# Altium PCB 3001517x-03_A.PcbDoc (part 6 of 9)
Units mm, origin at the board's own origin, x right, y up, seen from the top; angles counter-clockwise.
Board outline 100 x 72 mm, 10 copper layers (Top, GND_2, Signal_3, Signal_4, PWR_5, GND_6, Signal_7, Signal_8, GND_9, Bottom), stack 1.6 mm thick; 602 components, 497 nets, 2372 pads, 1602 vias.
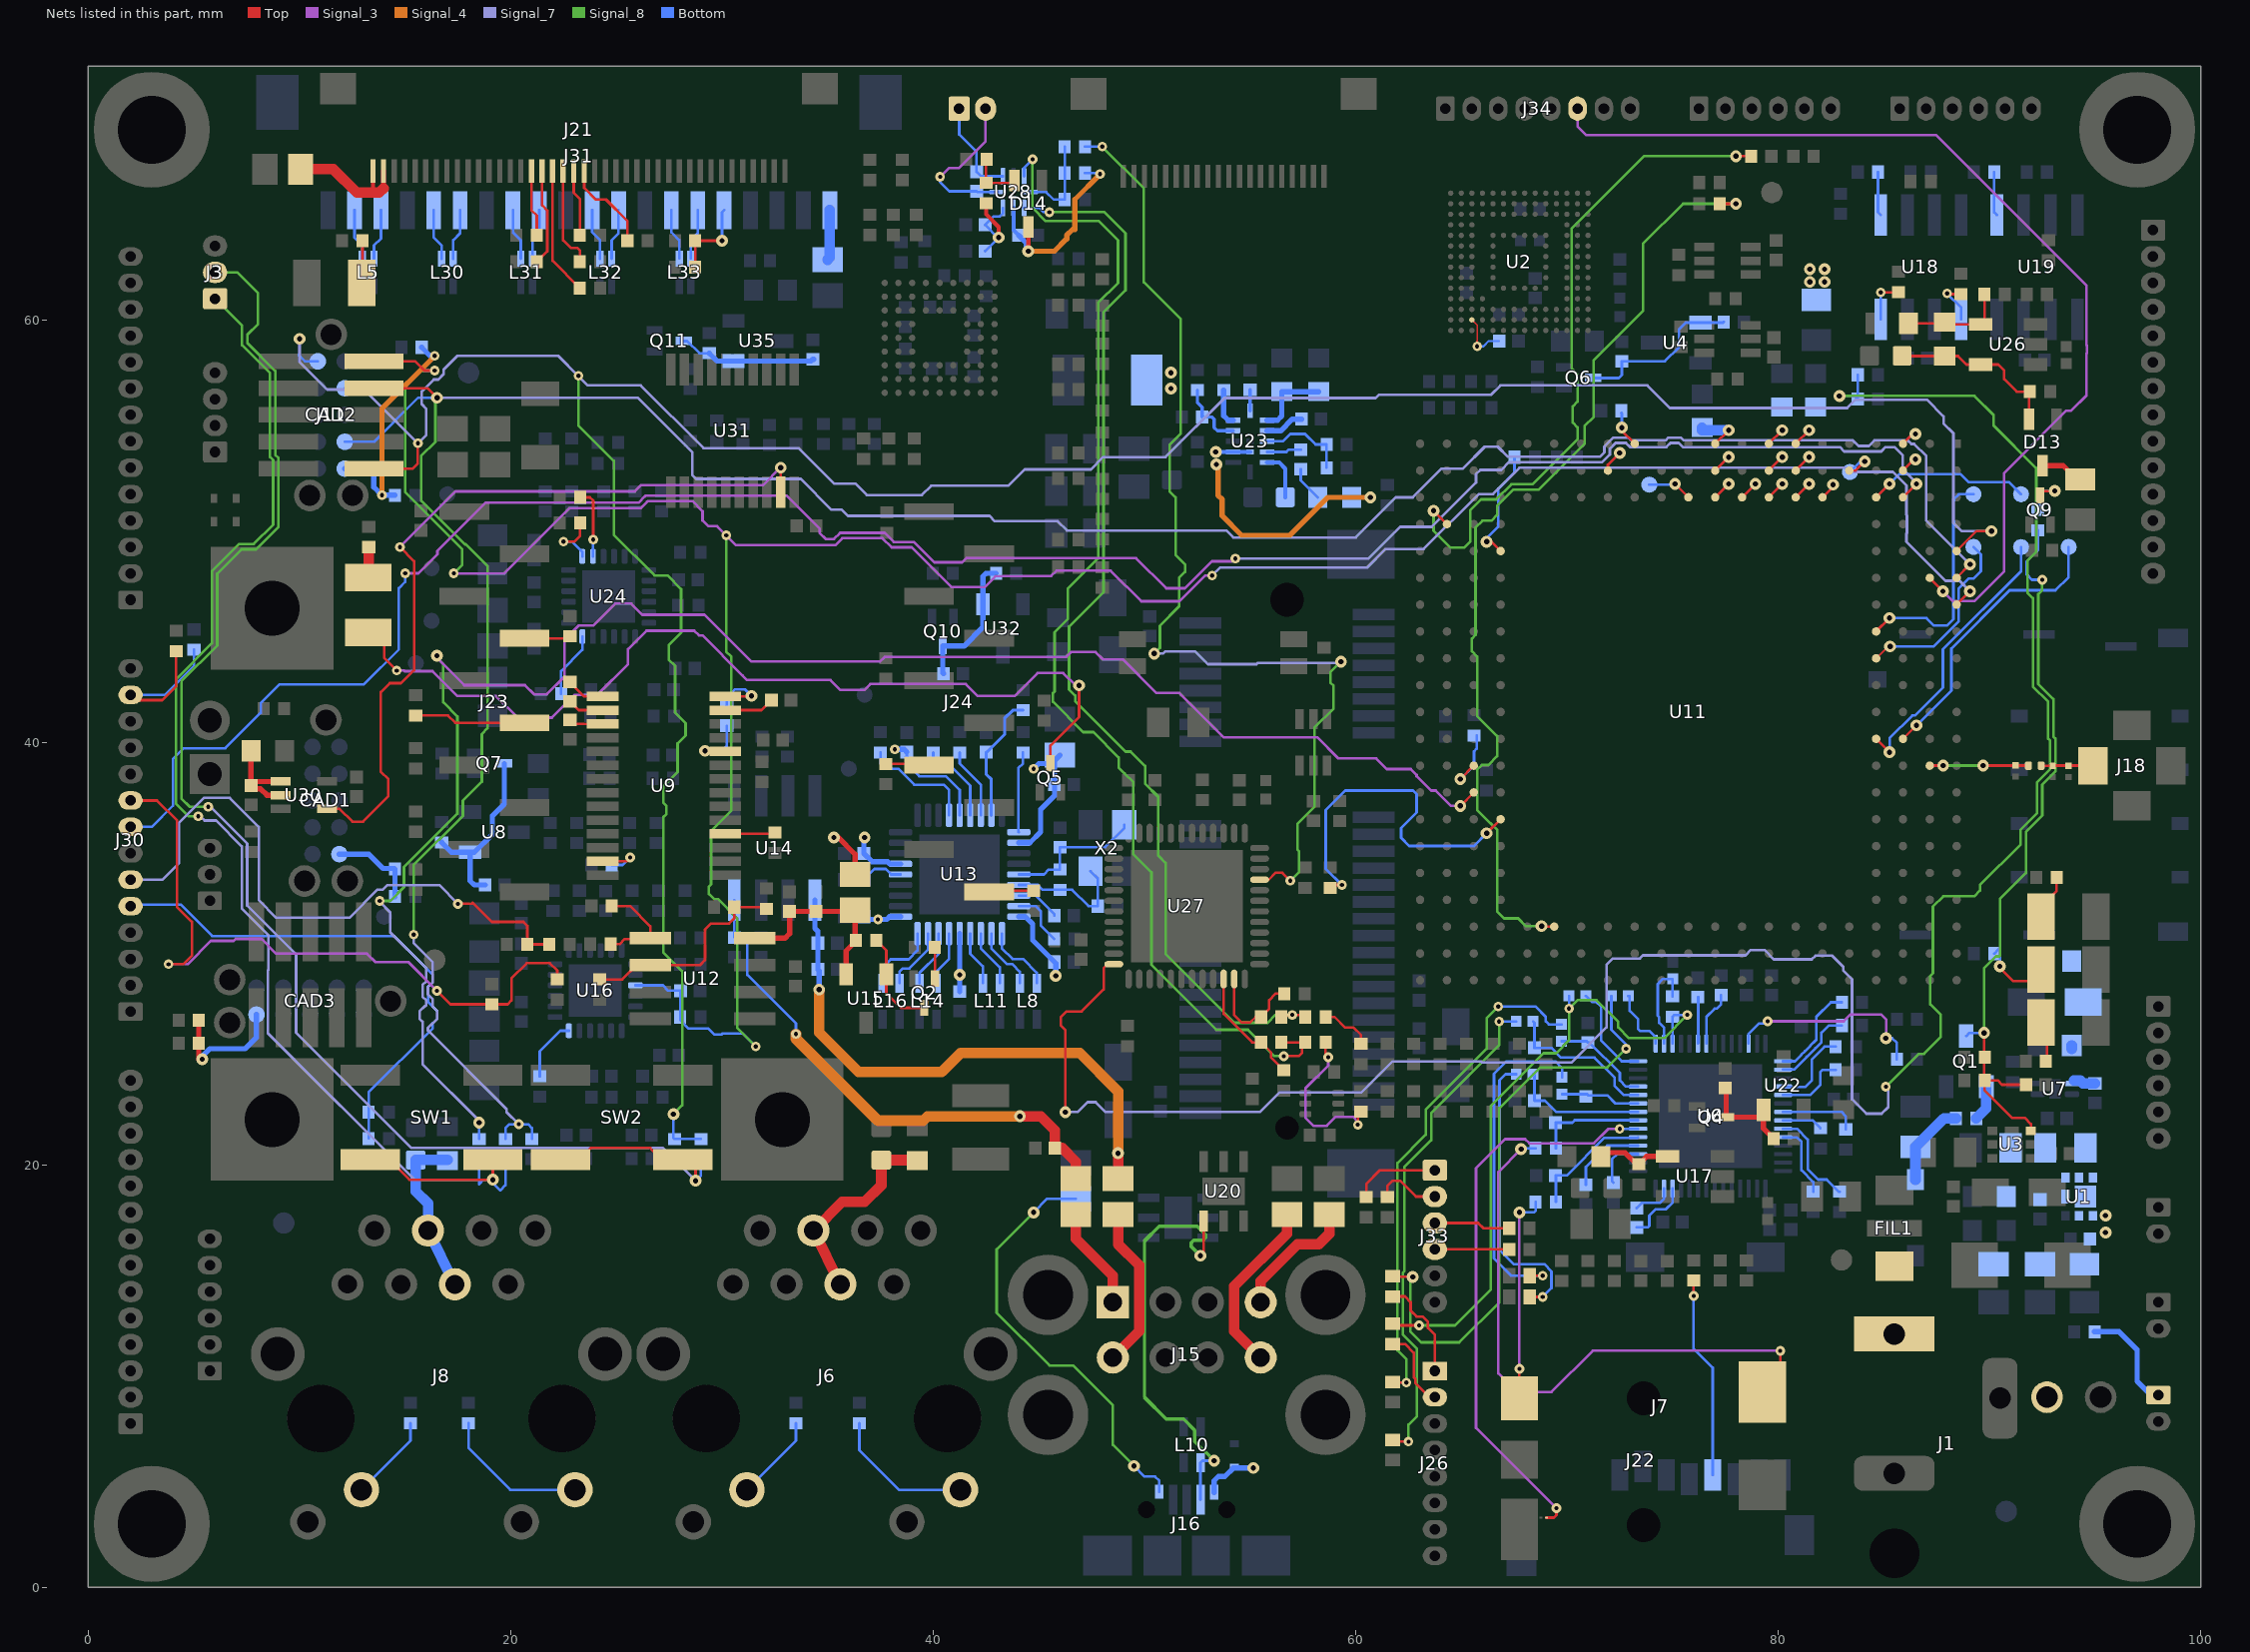
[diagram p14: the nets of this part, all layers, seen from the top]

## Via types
v1: diameter 0.56, hole 0.25, Top to Bottom, tented both sides, 1002 vias
v2: diameter 0.46, hole 0.2, Top to Bottom, tented both sides, 468 vias
v3: diameter 0.457, hole 0.2, Top to Bottom, tented both sides, 132 vias

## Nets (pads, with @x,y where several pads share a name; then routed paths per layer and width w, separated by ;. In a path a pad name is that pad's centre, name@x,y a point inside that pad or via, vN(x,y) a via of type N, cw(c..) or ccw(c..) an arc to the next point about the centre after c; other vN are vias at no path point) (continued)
MCA_IO3: J30.8 U11.C3 | length 102.6
  Top w0.119: U11.C3@85.91,51.6 v1(86.545,52.235)
  Signal_3 w0.127: v3(15,48) 15.625,48 16.524,48.9 16.524,49.072 18.8,51.348 21.147,51.348 21.149,51.346 26.056,51.346 26.345,51.634 26.387,51.676 33.067,51.676 34.629,50.114 34.629,49.905 34.905,49.629 35.295,49.629 35.57,49.905 35.588,49.922 37.699,49.922 38.133,49.488 39.086,49.488 40.049,48.526 41.376,48.526 41.571,48.72 49.606,48.72 51.034,47.293 51.91,47.293 53.191,48.573 54.173,48.573 v2(54.3,48.7)
  Signal_7 w0.127: v2(54.3,48.7) 60.6,48.7 62.1,50.2 63.6,50.2 65.7,52.3 65.7,52.7 65.9,52.9 66.9,52.9 67.267,53.267 71.672,53.267 72.029,53.625 72.029,53.895 72.305,54.17 72.795,54.17 72.99,53.976 74.71,53.976 74.905,54.17 75.295,54.17 75.49,53.976 82.93,53.976 83.13,53.775 84.88,53.775 85.08,53.976 85.5,53.976 85.9,53.575 85.9,52.929 86.545,52.284 v1(86.545,52.235)
  Bottom w0.119: J30.8@2,36 3,36 4,37 4,39.2 4.522,39.722 6.482,39.722 8.166,41.407 8.166,41.851 9.065,42.75 13.05,42.75 14.7,44.4 14.7,47.3 15,47.6 v3(15,48)
MCA_IO5: J34.6 U11.B6 | length 47.9
  Top w0.125: U11.B6@87.18,47.79 87.18,47.77 v1(87.8,47.15)
  Signal_3 w0.125: J34.6@70.5,70 70.5,69.155 70.902,68.753 87.47,68.753 94.6,61.623 94.6,58.793 94.62,58.793 94.62,58.426 94.6,58.407 94.6,56.432 93.868,55.7 93.65,55.7 90.7,52.75 90.7,48.106 89.279,46.685 88.264,46.685 v1(87.8,47.15)
MCA_RESET_N: CAD2.10 J11.10 R97.1 R98.2 U11.A5 | length 145.3
  Top w0.119: J11.10@13.532,52.96 15.36,52.96 15.6,53.2 v2(15.6,54.159) ; U11.A5@88.45,49.06 89.39,50 v1(90.1,50)
  Signal_8 w0.127: v2(23.2,57.35) 23.2,55 24.88,53.32 24.88,49.82 26.8,47.9 27.42,47.9 28.066,47.254 28.066,45.187 27.479,44.6 27.479,43.921 27.779,43.621 27.779,41.404 28.271,40.913 28.271,40.322 27.9,39.951 27.9,39.178 27.896,39.175 27.896,38.596 27.22,37.92 27.22,37.145 27.37,36.995 27.37,36.605 27.22,36.455 27.22,30.072 28.119,29.173 28.119,22.819 v1(27.7,22.4)
  Signal_7 w0.127: v1(10,59.1) 10,58 11.3,56.7 13.059,56.7 v2(15.6,54.159) 16,54.559 16,55.792 15.787,56.006 15.787,56.616 16.35,57.179 16.574,57.179 16.82,57.426 16.82,57.65 17.47,58.3 22.25,58.3 v2(23.2,57.35) 23.65,56.9 26.158,56.9 29.129,53.929 33.624,53.929 35.303,52.25 36.308,52.25 36.852,51.706 39.463,51.706 39.905,52.147 43.552,52.147 44.326,52.92 47.463,52.92 48.045,53.503 50.995,53.503 53.795,56.303 60.945,56.303 61.095,56.453 66.395,56.453 66.845,56.903 73.805,56.903 74.878,55.829 83.272,55.829 83.665,56.223 87.043,56.223 87.829,55.436 87.829,55.105 88.3,54.634 88.3,50.4 88.7,50 v1(90.1,50)
  Bottom w0.119: v1(10,59.1) 10,58.3 10.26,58.04 CAD2.10@10.865,58.04 ; v1(27.7,22.4) 27.7,21.28 R97.1@27.75,21.23 R98.2@29,21.23
MCA_SWD_CLK/PWR_IO: CAD2.4 J11.4 R83.1 R99.2 U11.A6 | length 134.9
  Top w0.119: J11.4@13.532,56.77 16.056,56.77 v1(16.509,56.317) ; U11.A6@88.45,47.79 v1(89.085,48.425)
  Signal_8 w0.127: v3(15.4,30.9) 15.4,34.191 17.728,36.52 17.728,37.238 18.63,38.139 18.63,40.395 18.9,40.665 18.9,48.35 17.871,49.379 17.826,49.379 15.755,51.45 15.755,53.555 16.429,54.229 16.429,56.237 v1(16.509,56.317)
  Signal_7 w0.127: v3(15.4,30.9) 15.4,30.5 16.304,29.596 16.304,28.645 16.08,28.42 16.08,28.072 16.304,27.847 16.304,27.491 16.521,27.274 16.521,26.926 16.08,26.485 16.08,26.364 19.8,22.644 19.8,22.5 v2(20.375,21.925) ; v1(16.509,56.317) 26.01,56.317 28.589,53.738 28.589,52.661 28.78,52.47 33.726,52.47 35.181,51.015 35.665,51.015 35.954,50.725 42.661,50.725 42.915,50.471 45.888,50.471 46.331,50.029 53.872,50.029 54.2,49.7 60,49.7 61.9,51.6 62.7,51.6 64.06,52.96 65.075,52.96 66.111,53.996 66.726,53.996 67.201,53.521 71.566,53.521 71.775,53.73 71.775,54 72.2,54.424 72.9,54.424 73.024,54.3 74.675,54.3 74.8,54.424 75.4,54.424 75.524,54.3 83.534,54.3 83.805,54.029 84.295,54.029 84.565,54.3 86.134,54.3 86.305,54.129 86.436,54.129 87.016,53.55 87.016,50.495 v1(89.085,48.425)
  Bottom w0.119: CAD2.4@12.135,54.23 13.53,54.23 15.617,56.317 v1(16.509,56.317) ; R99.2@19.75,21.23 19.75,21.75 19.925,21.925 v2(20.375,21.925) 20.825,21.925 21,21.75 R83.1@21,21.23
MCA_SWD_DIO/ETH1_RST: C18.2 CAD2.2 J11.2 R26.2 U11.A7 U16.15 | length 136.9
  Top w0.125: J11.2@13.532,58.04 15.46,58.04 15.9,57.6 v2(16.4,57.6) ; U11.A7@88.45,46.52 v1(89.085,47.155)
  Signal_3 w0.125: v2(17.3,48) 19.693,48 22.786,51.093 26.161,51.093 26.449,51.381 26.491,51.423 28.6,51.423 29.08,50.943 29.08,50.506 29.356,50.23 29.744,50.23 29.769,50.231 v3(30.2,49.8) 30.664,49.335 35.359,49.335 35.693,49.669 37.594,49.669 38.028,49.235 38.982,49.235 40.864,47.353 42.435,47.353 42.802,47.72 42.802,47.725 42.958,47.88 42.963,47.88 45.59,47.881 45.837,48.127 48.403,48.127 49.85,46.68 51.655,46.68 52.875,47.9 v2(53.2,47.9)
  Signal_8 w0.125: v2(16.4,57.6) 15.72,57.6 15,56.88 15,51.848 17.7,49.148 17.7,48.4 v2(17.3,48) ; v3(30.2,49.8) 30.2,44.3 30.431,44.068 30.431,36.761 29.482,35.811 29.482,33.275 29.38,33.174 29.38,32.826 29.626,32.58 29.813,32.58 30.719,31.674 30.719,26.481 v2(31.6,25.6)
  Signal_7 w0.125: v2(53.2,47.9) 53.573,48.274 60.531,48.274 61.411,49.153 63.223,49.153 65.828,51.758 66.508,51.758 67.75,53 83.2,53 83.4,52.8 85.429,52.8 86.075,52.154 86.075,50.771 86.1,50.746 86.1,49.914 86.075,49.889 86.075,49.501 87.928,47.648 88.592,47.648 v1(89.085,47.155)
  Bottom w0.125: CAD2.2@12.135,56.77 14.89,56.77 15.72,57.6 v2(16.4,57.6) ; U16.15@25.9,28.5 27.2,28.5 27.45,28.25 C18.2@28.04,28.25 28.02,28.23 R26.2@28.02,27 28.02,26.86 28.425,26.456 29.351,26.456 29.626,26.18 29.974,26.18 30.013,26.22 30.98,26.22 v2(31.6,25.6)
MIC_BIAS: C132.2 L19.2 R196.1 U6.45 | length 30.3
  Top w0.125: L19.2@61.75,12.48 61.83,12.4 v2(63,12.4)
  Signal_8 w0.125: v2(63,12.4) 64.7,12.4 66.4,14.1 66.4,22.8 68.887,25.287 69.494,25.287 70.1,25.893 v2(70.1,27.4) 70.5,27.8 71.4,27.8 72.43,26.77 72.43,26.505 72.936,26 74.6,26 v2(75.7,27.1)
  Bottom w0.125: v2(70.1,27.4) C132.2@70.1,28 ; U6.45@75,25.74 R196.1@75,27.02 75.08,27.1 v2(75.7,27.1)
MIC_N: J26.1 L24.1 | length 4.9
  Top w0.127: L24.1@61.75,13.77 62.33,13.77 62.6,13.5 62.6,13.1 62.88,12.821 63.174,12.821 63.421,12.574 63.421,12.28 63.75,11.95 J26.1@63.75,10.25
MIC_P: J26.2 L19.1 | length 3.8
  Top w0.125: L19.1@61.75,11.52 62.33,11.52 62.75,11.1 62.75,9.943 62.82,9.874 62.82,9.68 63.5,9 J26.2@63.75,9
NetC8_2: C8.2 C9.1 C10.2 R21.1 U7.1 | length 1.2
  Bottom w0.5: C8.2@93.9,25.5 C8.2@93.9,25.65 ; 94,24 94.3,24 94.44,23.86 C10.2@95,23.86
NetC20_1: C20.1 U9.24 | length 3.2
  Top w0.125: v1(29.2,39.6) 29.962,39.6 30.069,39.494 U9.24@30.15,39.575
  Bottom w0.125: v1(29.2,39.6) 29.787,39.6 29.894,39.494 30.225,39.825 C20.1@30.225,40.79
NetC20_2: C20.2 U9.28 | length 3.1
  Top w0.125: U9.28@30.15,42.175 31.375,42.175 v1(31.4,42.2)
  Bottom w0.125: C20.2@30.225,41.71 30.225,42.125 30.6,42.5 31.1,42.5 v1(31.4,42.2)
NetC21_2: C21.2 U9.27 | length 2.4
  Top w0.125: U9.27@30.15,41.525 31.865,41.525 C21.2@32.34,42
NetC23_1: C23.1 U9.2 | length 1.7
  Top w0.125: C23.1@22.8,41.94 23.215,41.525 U9.2@24.35,41.525
NetC23_2: C23.2 U9.1 | length 1.8
  Top w0.125: C23.2@22.8,42.86 23.485,42.175 U9.1@24.35,42.175
NetC24_1: C24.1 Q6.D R185.2 U4.G | length 8.2
  Bottom w0.125: Q6.D@71.24,57.25 72.45,57.25 72.6,57.4 C24.1@72.6,58.04 74.64,58.04 75.3,58.7 75.3,59.55 75.62,59.87 U4.G@76.32,59.87 77.39,59.87 R185.2@77.42,59.9
NetC25_2: C25.2 U9.3 | length 1.6
  Top w0.125: C25.2@22.8,41.06 22.985,40.875 U9.3@24.35,40.875
NetC26_1: C26.1 Q7.D R7.2 U8.G | length 8.7
  Bottom w0.25: R7.2@16.725,35.27 17.195,34.8 U8.G@18.075,34.8 ; C26.1@18.79,33.25 18.275,33.25 18.075,33.45 U8.G@18.075,34.8 ; Q7.D@19.69,39 19.69,37.09 19.123,36.523 19.123,35.647 18.276,34.8 U8.G@18.075,34.8
NetC29_2: C29.2 J6.4 J6.5 R48.1 | length 9.8
  Top w0.5: J6.5@35.6,14.35 J6.4@34.33,16.89 35.69,18.25 36.75,18.25 37.541,19.041 C29.2@37.541,20.228 39.222,20.228 R48.1@39.25,20.2
NetC47_2: C47.2 J8.4 J8.5 R79.1 | length 7.9
  Bottom w0.5: R79.1@17,20.23 C47.2@15.5,20.23 15.5,18.75 16.08,18.17 J8.4@16.08,16.89 J8.5@17.35,14.35
NetC55_2: C55.2 R148.2 R224.1 R225.1 U1.4 U1.8
NetC56_2: C56.2 C57.2 C58.2 C59.2 R224.2 R279.1 U1.1 U1.2 U1.5 U1.6 U1.7
  other v1: 95.5,16.8 95.5,17.6 81.5,61.8 82.2,61.8 81.5,62.4 82.2,62.4
NetC61_2: C61.2 J18.1 L4.1 R5.2 | length 2.5
  Top w0.125: L4.1@92.45,38.9 92.458,38.892 C61.2@93,38.892 93.008,38.9 J18.1@94.908,38.9
NetC63_1: C63.1 R67.1 U13.32 X2.3 | length 6.7
  Bottom w0.125: U13.32@44.05,33.75 45.242,33.75 45.472,33.98 R67.1@46,33.98 C63.1@46,35.04 48.14,35.04 49.05,35.95 X2.3@49.05,36.1
NetC64_1: C64.1 R67.2 U13.33 X2.1 | length 5.9
  Bottom w0.125: U13.33@44.05,33.25 44.95,33.25 45.18,33.02 R67.2@46,33.02 46.58,33.02 47.35,32.25 C64.1@47.79,32.25 47.79,33.56 X2.1@47.45,33.9
NetC66_2: C66.2 C67.2 L9.2 R72.1 U12.8 U15.S | length 9.2
  Top w0.25: U12.8@31.545,30.729 32.979,30.729 33.2,30.95 C66.2@33.2,32 C67.2@34.45,32 36.25,32 L9.2@36.3,32.05 36.3,30.67 R72.1@36.345,30.625 36.345,30.595 35.875,30.125 U15.S@35.875,29.025
NetC68_2: C68.2 C71.2 L7.2 U14.8 | length 25.2
  Top w0.5: v1(44.1,22.3) 45.1,22.3 45.76,21.64 C71.2@45.76,20.8 46.1,20.8 46.75,20.15 L7.2@46.75,19.35
  Signal_4 w0.5: v2(33.5,26.2) 33.5,25.971 37.378,22.093 39.522,22.093 39.729,22.3 v1(44.1,22.3)
  Bottom w0.125: U14.8@30.585,32.53 30.585,30.775 C68.2@30.6,30.76 31.048,30.76 31.2,30.608 31.2,29 33.5,26.7 v2(33.5,26.2)
NetC69_2: C69.2 C70.2 L6.2 U14.5 | length 26.5
  Top w0.5: L6.2@48.75,19.35 v1(48.75,20.55)
  Signal_4 w0.5: v1(34.6,28.3) 34.6,26.264 36.464,24.4 40.4,24.4 41.3,25.3 46.932,25.3 48.75,23.482 v1(48.75,20.55)
  Bottom w0.25: U14.5@34.395,32.53 34.395,31.205 34.54,31.06 C70.2@34.54,30.5 C69.2@34.54,29.25 34.6,29.19 v1(34.6,28.3)
NetC72_2: C72.2 C73.2 C74.2 C75.2 C76.2 C77.2 L17.1 U13.5 U13.10 U13.15 U13.23 U13.29 U13.36 | length 22.8
  Bottom w0.125: C77.2@38.75,39.54 38.75,38.978 39.328,38.4 40.6,38.4 41.25,37.75 U13.23@41.25,36.55
  Bottom w0.25: C74.2@36.71,31.75 36.843,31.617 v2(37.383,31.617) 37.8,31.617 37.933,31.75 U13.10@38.45,31.75 ; v1(36.75,35.5) 36.71,35.46 C73.2@36.71,34.75 37.11,34.35 37.816,34.35 37.818,34.348 37.851,34.348 37.949,34.25 U13.15@38.45,34.25 ; v2(38.175,39.675) 38.615,39.675 C77.2@38.75,39.54 ; C75.2@41.25,28.21 v1(41.25,29) U13.5@41.25,30.95 ; U13.36@44.05,31.75 44.35,31.75 44.7,31.4 44.7,30.64 C76.2@45.74,29.6 45.8,29.54 v1(45.8,28.95) ; U13.29@44.05,35.25 44.576,35.25 45.087,35.762 45.087,36.829 45.74,37.482 C72.2@45.74,38 L17.1@45.74,39.14 ; v2(44.75,38.75) 45,39 45.6,39 L17.1@45.74,39.14 ; L17.1@46,39.4 L17.1@45.74,39.14
NetC78_2: C78.2 U13.14 | length 2.1
  Bottom w0.125: C78.2@36.71,33.5 37.218,34.008 37.746,34.008 38.004,33.75 U13.14@38.45,33.75
NetC79_2: C79.2 U13.34 | length 2.1
  Bottom w0.125: U13.34@44.05,32.75 44.85,32.75 45.74,31.86 C79.2@45.74,31.8
NetC80_2: C80.2 L4.2 U11.B13 | length 4.7
  Top w0.125: U11.B13@87.18,38.9 v1(87.815,38.9) ; v1(89.7,38.9) L4.2@91.85,38.9
  Signal_8 w0.125: v1(87.815,38.9) v1(89.7,38.9)
NetC88_1: C88.1 U6.27 | length 2
  Bottom w0.125: C88.1@73.3,17.96 73.54,18.2 74.4,18.2 74.6,18.4 U6.27@74.6,18.88
NetC88_2: C88.2 U6.26 | length 3.1
  Bottom w0.125: C88.2@73.3,17.04 73.832,17.04 73.9,17.108 73.9,17.6 74.2,17.9 74.692,17.9 75,18.208 U6.26@75,18.88
NetC90_2: C90.2 U6.32 | length 3.7
  Bottom w0.125: C90.2@70.9,19.06 70.9,19.9 71.91,20.91 U6.32@73.37,20.91
NetC95_2: C95.2 U6.31 | length 2.5
  Bottom w0.125: C95.2@72.2,19.16 72.132,19.228 72.132,20.273 72.377,20.518 72.723,20.518 72.741,20.5 72.751,20.51 U6.31@73.37,20.51
NetC96_1: C96.1 U6.48 | length 2.2
  Bottom w0.125: U6.48@76.2,25.74 76.218,25.758 76.218,27.94 C96.1@76.2,27.94
NetC97_2: C97.2 U6.49 | length 2.6
  Bottom w0.125: U6.49@76.6,25.74 76.6,27 77,27.4 77.1,27.4 77.3,27.6 C97.2@77.3,28.04
NetC107_1: C107.1 U23.10 | length 1.6
  Bottom w0.125: U23.10@55.8,53.75 56.725,53.75 56.835,53.86 C107.1@57.4,53.86
NetC107_2: C107.2 R142.1 | length 1.7
  Bottom w0.125: C107.2@57.4,52.94 57.4,52.4 R142.1@58.2,51.6
NetC108_1: C108.1 U23.8 | length 1.9
  Bottom w0.25: U23.8@55.8,54.75 56.45,54.75 57,55.3 C108.1@57.44,55.3
NetC109_2: C109.2 U23.11 | length 2.3
  Bottom w0.2: U23.11@55.8,53.25 56.378,53.25 56.67,52.958 C109.2@56.67,51.6
NetC110_2: C110.2 U23.6 | length 1
  Bottom w0.15: U23.6@55,55.7 C110.2@55,56.69
NetC121_2: C121.2 Q1.3 R14.2 R120.1 R126.1 U3.3 | length 35.4
  Top w0.125: R126.1@89.75,23.939 v1(89.75,26.25) ; C121.2@91.74,23.8 90.6,23.8 90.4,24 R126.1@89.78,24 89.78,23.52 91.07,22.23 91.67,22.23 91.968,21.932 U3.3@91.968,21.617
  Signal_8 w0.125: v1(89.75,26.25) 89.75,29.314 90.306,29.87 90.47,29.87 90.5,29.9 90.5,32.585 91.73,33.815 91.73,35.764 92.502,36.535 92.502,38.002 93.125,38.626 93.125,40.183 93.03,40.279 93.03,42.049 92.318,42.761 92.318,47.018 92.5,47.2 v2(92.5,47.7)
  Bottom w0.125: Q1.3@88.9,26.1 89.05,26.25 v1(89.75,26.25) ; R120.1@92.3,50.045 92.3,49.1 91.764,48.564 91.764,47.954 92.018,47.7 v2(92.5,47.7)
NetC125_2: C125.2 U2.C2 | length 2.5
  Top w0.076: U2.C2@65.5,60 65.75,59.75 65.75,59
  Top w0.1: v3(65.75,58.75) 65.75,59
  Bottom w0.1: v3(65.75,58.75) 66.05,58.75 66.3,59 C125.2@66.79,59
NetC130_2: C130.2 D13.2 R179.2 R182.1 U26.5 | length 8.3
  Top w0.125: C130.2@85.87,58.3 85.883,58.287 R179.2@87.88,58.287 88.513,58.287 88.913,57.887 U26.5@89.58,57.887 90.413,57.887 90.7,57.6 90.7,57.2 91.3,56.6 R182.1@91.92,56.6 91.872,56.552 D13.2@91.872,55.3
NetC131_1: C131.1 R196.2 U6.44 | length 4.6
  Bottom w0.125: U6.44@74.6,25.74 74.6,26.492 74.369,26.723 74.369,26.994 74.3,27.064 74.3,28.56 74.54,28.8 C131.1@75,28.8 R196.2@75,27.98
NetC132_1: C132.1 U6.42 | length 4.7
  Bottom w0.125: C132.1@70.9,28 71.181,27.719 71.374,27.719 71.619,27.474 71.619,25.881 72.59,24.91 U6.42@73.37,24.91
NetC133_1: C133.1 U6.43 | length 3.1
  Bottom w0.125: C133.1@72.9,28 72.97,28 72.97,27.294 73.369,26.894 73.369,26.431 73.47,26.33 73.92,26.33 74.2,26.05 U6.43@74.2,25.74
NetC133_2: C133.2 L24.2 | length 28
  Top w0.125: L24.2@61.75,14.73 61.78,14.7 v1(62.7,14.7)
  Signal_8 w0.125: v1(62.7,14.7) 62.58,14.581 62.58,12.12 63.1,11.6 64.9,11.6 66.8,13.5 66.8,22.682 68.737,24.62 71.919,24.62 v2(72.8,25.5)
  Bottom w0.125: C133.2@72.1,28 72.1,26.4 72.8,25.7 v2(72.8,25.5)
NetC134_1: C134.1 C135.1 U6.39 | length 4.7
  Bottom w0.125: C135.1@69.75,25.85 70.94,25.85 C134.1@71,25.79 71.066,25.79 72.502,24.354 72.502,23.998 72.79,23.71 U6.39@73.37,23.71
NetC135_2: C135.2 L20.2 | length 24.1
  Top w0.125: L20.2@61.75,9.73 61.78,9.7 v2(62.4,9.7)
  Signal_8 w0.125: v2(62.4,9.7) 62.4,10.8 61.978,11.222 61.978,20.088 63.32,21.43 63.32,22.62 66.2,25.5 66.2,26.95 v2(66.75,27.5)
  Bottom w0.125: v2(66.75,27.5) 68.5,27.5 69,27 69,26.8 69.15,26.65 C135.2@69.75,26.65
NetC136_1: C136.1 C138.1 U6.38 | length 7.3
  Bottom w0.125: C136.1@68.4,26.79 68.46,26.73 C138.1@68.46,25.54 69.26,25.54 69.717,25.083 71.31,25.083 72.25,24.143 72.25,23.75 72.69,23.31 U6.38@73.37,23.31
NetC136_2: C136.2 L21.2 | length 23.8
  Top w0.125: L21.2@61.75,6.98 61.83,6.9 v2(62.5,6.9)
  Signal_8 w0.125: v2(62.5,6.9) 62.5,7.7 62.9,8.1 62.9,11.3 62.23,11.97 62.23,14.894 62.3,14.964 62.3,19.887 63.574,21.161 63.574,22.459 66.79,25.675 v2(66.79,26.79)
  Bottom w0.125: v2(66.79,26.79) C136.2@67.6,26.79
NetC137_1: C137.1 R197.1 U6.35 | length 5.2
  Bottom w0.125: R197.1@69.48,20.79 69.48,21.98 C137.1@69.46,22 70.25,22 70.368,22.118 73.37,22.118 U6.35@73.37,22.11
NetC139_1: C139.1 R198.1 U6.33 | length 5.9
  Bottom w0.125: R198.1@69.48,18.25 69.48,19.48 C139.1@69.46,19.5 70,19.5 71.782,21.282 73.342,21.282 U6.33@73.37,21.31
NetC140_1: C140.1 C141.1 U6.37 | length 3.8
  Bottom w0.125: C141.1@69.767,23.35 70.957,23.35 71.017,23.29 71.91,23.29 72.29,22.91 U6.37@73.37,22.91
NetC141_2: C141.2 L22.2 | length 16
  Top w0.125: L22.2@68.23,14.75 v2(68.85,14.75)
  Bottom w0.125: v2(68.85,14.75) 67.375,14.75 66.55,15.575 66.55,24.317 67.133,24.9 69.45,24.9 69.767,24.583 C141.2@69.767,24.15
NetC142_1: C142.1 C143.1 U6.36 | length 6.4
  Bottom w0.125: C142.1@68.4,24.29 68.46,24.23 C143.1@68.46,23.04 68.96,23.04 69.49,22.51 U6.36@73.37,22.51
NetC142_2: C142.2 L23.2 | length 13.8
  Top w0.125: L23.2@68.23,13.75 v2(68.85,13.75)
  Bottom w0.125: C142.2@67.6,24.29 67.09,24.29 66.805,24.005 66.805,15.97 67.475,15.3 68.925,15.3 69.27,14.955 69.27,14.17 v2(68.85,13.75)
NetC147_1: C147.1 J36.2 U28.8 | length 7.5
  Signal_3 w0.125: v2(40.325,66.775) 40.745,67.195 41.22,67.195 42.476,68.451 J36.2@42.476,70
  Bottom w0.125: v2(40.325,66.775) 40.325,66.525 40.76,66.09 C147.1@42.05,66.09 ; C147.1@42.09,66.05 U28.8@43.05,66.05
NetC147_2: C147.2 J36.1 U28.1 | length 4.7
  Bottom w0.125: J36.1@41.226,70 41.226,68.774 42.05,67.95 C147.2@42.05,67.01 42.26,66.8 U28.1@43.3,66.8
NetC149_1: C149.1 Q4.D R128.2 U22.G | length 4.4
  Top w0.25: C149.1@77.5,23.64 77.54,23.6 Q4.D@77.54,22.26 79.308,22.26 79.308,21.72 R128.2@79.778,21.25
NetC152_2: C152.2 R213.2 U30.1 U30.2 | length 4.7
  Top w0.25: R213.2@7.7,39.6 C152.2@7.7,37.96 ; U30.2@9.1,37.5 8.458,37.5 8.158,37.8 7.86,37.8 C152.2@7.7,37.96 ; U30.1@9.1,38.15 7.89,38.15 C152.2@7.7,37.96
NetC154_1: C154.1 Q10.D R240.2 U32.G | length 6.7
  Bottom w0.25: C154.1@40.49,43.25 40.45,43.29 Q10.D@40.45,44.56 41.46,44.56 42.349,45.449 U32.G@42.349,46.539 42.349,47.849 42.5,48 R240.2@42.97,48
NetC155_2: C155.2 R242.2 U13.26 | length 6.1
  Bottom w0.15: U13.26@42.75,36.55 42.75,38.25 42.5,38.5 C155.2@42.5,39.54 42.548,39.54 43.375,40.367 43.375,41.133 43.762,41.52 R242.2@44.25,41.52
NetC158_1: C158.1 Q11.D R251.2 U35.G | length 6.6
  Bottom w0.125: Q11.D@28.19,59 28.349,59 28.929,58.42 R251.2@29.4,58.42
  Bottom w0.25: R251.2@29.4,58.42 29.77,58.05 U35.G@30.55,58.05 34.21,58.05 C158.1@34.3,58.14 C158.1@34.346,58.14
NetCAD1_5: CAD1.5 R149.2 R151.2 | length 4.2
  Bottom w0.25: CAD1.5@11.885,34.71 13.272,34.71 13.95,34.032 14.48,34.032 R149.2@14.512,34 14.512,32.708 R151.2@14.52,32.7
NetCAD2_5: CAD2.5 R150.2 R152.2 | length 11.7
  Signal_4 w0.25: v2(13.9,51.7) 13.9,55.8 v2(16.4,58.3)
  Bottom w0.25: CAD2.5@12.135,52.96 13.267,52.96 13.517,52.71 13.517,52.083 v2(13.9,51.7) R152.2@14.52,51.7 ; R150.2@15.78,58.7 16.18,58.3 v2(16.4,58.3)
NetCAD3_5: CAD3.5 R268.2 R269.2 | length 6.2
  Top w0.25: R268.2@5.23,26.85 R269.2@5.23,25.75 5.23,25.02 5.25,25 v1(5.391,25)
  Bottom w0.25: v1(5.391,25) 5.391,25.141 5.75,25.5 7.42,25.5 7.96,26.04 CAD3.5@7.96,27.115
NetD1_A: D1.A R12.1 | length 2.2
  Top w0.125: D1.A@92.45,31.75 92.45,32.25 93.18,32.98 R12.1@93.18,33.6
NetD2_K: D2.K R11.1 R13.1 | length 4
  Bottom w0.5: D2.K@86.5,19.3 R11.1@86.5,20.85 87.85,22.2 R13.1@88.42,22.2
NetD3_A: D3.A R20.1 | length 3.6
  Top w0.125: v1(90.5,29.4) 90.5,29.336 91.136,28.7 91.9,28.7 D3.A@92.45,29.25
  Bottom w0.125: R20.1@90.23,30 90.43,30.2 90.5,30.13 v1(90.5,29.4)
NetD4_A: D4.A R119.1 | length 2
  Top w0.125: D4.A@12.95,61.75 12.98,61.78 R119.1@12.98,63.75
NetD10_2: D10.2 J16.1 L9.1 | length 4.9
  Top w0.25: v1(35.3,35.5) 35.5,35.5 36.3,34.7 L9.1@36.3,33.75
  Bottom w0.25: J16.1@53.3,4.5 53.3,5.051 53.499,5.25 53.8,5.25 54.2,5.65 v1(55.15,5.65)
NetD11_A: D11.A R133.2 | length 1.5
  Top w0.5: D11.A@13.25,47.8 13.275,47.825 R133.2@13.275,49.245
NetD11_K: D11.K Q5.D | length 44.6
  Top w0.125: D11.K@13.25,45.2 14,45.2 14,44 v3(14.6,43.4) ; Q5.D@45.55,39.015 45.55,39.857 46.9,41.207 v1(46.9,42.7)
  Signal_3 w0.125: v3(14.6,43.4) 14.939,43.4 14.97,43.37 16.294,43.37 17.464,42.2 19.3,42.2 20.325,41.175 21.944,41.175 23.017,42.248 24.091,42.248 25.552,43.709 25.552,44.41 26.427,45.285 28.685,45.285 28.905,45.064 29.079,45.064 30.981,43.163 31.194,42.95 35.132,42.95 35.601,42.48 36.73,42.48 37.016,42.766 41.534,42.766 42.1,42.2 43.851,42.2 44.937,43.286 46.144,43.286 46.73,42.7 v1(46.9,42.7)
  Signal_8 w0.125: v3(14.6,43.4) v3@14.618,43.418
NetD12_A: D12.A R23.1 | length 2.1
  Top w0.125: D12.A@92.45,26.75 92.73,26.47 R23.1@92.73,24.75
NetD13_3: D13.3 R261.1 | length 2
  Top w0.25: D13.3@92.522,53.1 93.5,53.1 94.15,52.45 R261.1@94.3,52.45
NetD14_2: D14.2 R203.1 R204.1 | length 2.5
  Top w0.125: R203.1@42.53,67.6 42.5,67.57 R204.1@42.5,66.48 43.73,66.48 D14.2@43.85,66.6
NetFIL1_1: FIL1.1 J1.1 J35.1
NetJ2_1: J2.1 R8.1 | length 5.1
  Bottom w0.25: R8.1@94.98,12.1 96.15,12.1 97,11.25 97,9.75 97.65,9.1 J2.1@98,9.1
NetJ3_1: J3.1 R99.1 R167.1 SW1.3 SW1.4 | length 65.5
  Top w0.125: SW1.3@13.35,20.25 14.25,20.25 15.2,19.3 v1(19.15,19.3) SW1.4@19.15,20.25
  Signal_8 w0.125: v3(5.2,36.5) 4.75,36.5 4.157,37.093 4.157,42.998 5.85,44.69 5.85,48.092 7.151,49.393 7.837,49.393 8.748,50.304 8.748,53.36 8.6,53.508 8.6,57.48 7.278,58.801 7.278,59.722 J3.1@6,61
  Signal_7 w0.125: v3(5.2,36.5) 5.3,36.5 5.5,36.3 6.05,36.3 7.269,35.081 7.269,32.131 8.52,30.88 8.52,29.226 8.5,29.207 8.5,26.236 15.436,19.3 v1(19.15,19.3)
  Bottom w0.125: R167.1@18.5,20.27 18.5,19.09 18.71,19.3 v1(19.15,19.3) 19.15,19.145 19.5,18.795 19.75,19.045 R99.1@19.75,20.27
NetJ3_2: J3.2 R98.1 SW2.3 SW2.4 | length 74.4
  Top w0.125: SW2.3@22.35,20.25 23.242,20.25 23.792,20.8 26.6,20.8 27.15,20.25 SW2.4@28.15,20.25 28.75,20.25 v1(28.75,19.25)
  Signal_8 w0.125: v3(5.674,36.953) 4.797,36.953 4.409,37.341 4.409,42.893 6.102,44.586 6.102,47.987 7.255,49.141 7.941,49.141 9,50.2 9,53.464 8.852,53.612 8.852,57.584 7.53,58.905 7.53,59.294 8.031,59.794 8.031,61.269 7.05,62.25 J3.2@6,62.25
  Signal_7 w0.125: v3(5.674,36.953) 5.674,37.062 7.521,35.215 7.521,32.279 9.833,29.967 9.833,26.253 15.286,20.8 27.2,20.8 v1(28.75,19.25)
  Bottom w0.125: J3.2@6,62.25 J3.2@6.02,62.27 ; v1(28.75,19.25) 29,19.5 R98.1@29,20.27
NetJ6_10: J6.10 R43.1 | length 4.1
  Bottom w0.125: J6.10@31.18,4.62 33.5,6.94 R43.1@33.5,7.77
NetJ6_12: J6.12 R52.2 | length 6.8
  Bottom w0.125: R52.2@36.5,7.77 36.5,6.5 38.38,4.62 J6.12@41.29,4.62
NetJ7_5: J7.5 R35.2 | length 9.6
  Top w0.125: v2(76,13.8) R35.2@76,14.52
  Bottom w0.125: v2(76,13.8) 76,11.3 76.9,10.4 J7.5@76.9,5.325
NetJ8_10: J8.10 R76.1 | length 4.1
  Bottom w0.125: J8.10@12.93,4.62 15.25,6.94 R76.1@15.25,7.77
NetJ8_12: J8.12 R124.2 | length 7
  Bottom w0.125: R124.2@18,7.77 18,6.6 19.98,4.62 J8.12@23.04,4.62
NetJ15_A1: J15.A1 L7.1 | length 4.9
  Top w0.5: L7.1@46.75,17.65 46.75,16.5 48.5,14.75 J15.A1@48.5,13.5
NetJ15_A4: J15.A4 L13.2 | length 6.1
  Top w0.5: J15.A4@55.5,13.5 55.5,14.5 57.25,16.25 58.25,16.25 58.75,16.75 L13.2@58.75,17.65
NetJ15_B1: J15.B1 L6.1 | length 7.7
  Top w0.5: J15.B1@48.5,10.88 49.75,12.13 49.75,15.25 48.75,16.25 L6.1@48.75,17.65
NetJ15_B4: J15.B4 L12.2 | length 8.3
  Top w0.5: J15.B4@55.5,10.88 54.25,12.13 54.25,14.25 56.75,16.75 L12.2@56.75,17.65
NetJ16_5: J16.5 L15.2 | length 20.4
  Signal_8 w0.125: v1(44.75,17.75) 43,16 43,13 45.5,10.5 46.624,10.5 48.5,8.624 48.5,6.75 v1(49.5,5.75)
  Bottom w0.125: v1(44.75,17.75) 45.4,18.4 L15.2@46.75,18.4 ; v1(49.5,5.75) 50,5.25 50.499,5.25 50.7,5.049 J16.5@50.7,4.525
NetJ21_20: J21.20 R41.2 | length 4.4
  Top w0.125: J21.20@23.476,67.05 23.476,66.247 24.025,65.698 24.504,65.698 25.52,64.683 R41.2@25.52,63.75
NetJ21_21: J21.21 R207.2 | length 3.2
  Top w0.125: J21.21@22.976,67.05 22.976,66.024 23.27,65.73 R207.2@23.27,64
NetJ21_22: J21.22 R208.2 | length 4.8
  Top w0.125: J21.22@22.476,67.05 22.476,63.774 22.85,63.4 23.158,63.4 23.27,63.288 R208.2@23.27,62.75
NetJ21_23: J21.23 R209.2 | length 6.1
  Top w0.125: J21.23@21.976,67.05 21.976,62.794 R209.2@23.27,61.5
NetJ21_24: J21.24 R210.2 | length 4.6
  Top w0.125: R210.2@21.23,62.75 21.724,63.244 21.724,65.176 21.482,65.418 21.482,67.044 J21.24@21.476,67.05
NetJ21_25: J21.25 R211.2 | length 3.2
  Top w0.125: J21.25@20.976,67.05 20.976,65.2 21.23,64.946 R211.2@21.23,64
NetJ21_39: J21.39 J21.40 L18.2 | length 6.3
  Top w0.2: 13.476,66.024 J21.40@13.476,67.05
  Top w0.25: 13.974,66.224 J21.39@13.974,67.05
  Top w0.5: L18.2@10.05,67.131 11.6,67.131 12.708,66.024 13.476,66.024 ; 13.5,66.024 13.774,66.024 13.974,66.224
NetJ22_2: J22.2 R197.2 | length 28.7
  Top w0.125: J22.2@79.25,9.25 80.1,10.1 v2(80.1,11.2)
  Signal_3 w0.125: v1(67.83,20.75) 66.75,19.67 66.75,10.125 67.625,9.25 69.275,9.25 71.225,11.2 v2(80.1,11.2)
  Bottom w0.125: v1(67.83,20.75) 67.79,20.79 R197.2@68.52,20.79
NetJ22_3: J22.3 R198.2 | length 10
  Top w0.125: J22.3@67.75,8.95 v2(67.75,10.35)
  Signal_3 w0.125: v2(67.75,10.35) v1(67.75,17.75)
  Bottom w0.125: v1(67.75,17.75) 68.45,17.75 68.52,17.82 R198.2@68.52,18.25
NetJ23_4: J23.4 R84.2 | length 2.2
  Top w0.125: J23.4@20.65,44.925 22.705,44.925 R84.2@22.8,45.02
NetJ23_6: J23.6 R101.2 | length 5.3
  Top w0.125: R101.2@15.5,41.27 17.03,41.27 17.375,40.925 J23.6@20.65,40.925
NetJ24_7: J24.7 R135.1 | length 2.1
  Top w0.125: R135.1@37.75,38.98 39.745,38.98 J24.7@39.8,38.925
NetJ24_10: J24.10 R130.1 | length 2
  Top w0.125: J24.10@42.705,32.98 R130.1@44.75,32.98
NetJ30_5: J30.5 R3.1 R4.1 | length 25.1
  Bottom w0.125: J30.5@2,32.25 2.07,32.32 4.38,32.32 5.867,30.833 14.467,30.833 16.304,28.996 16.304,28.643 16.081,28.42 16.081,27.713 16.52,27.274 16.52,26.926 16.304,26.711 16.304,26.471 13.27,23.437 R4.1@13.27,22.5 R3.1@13.27,21.25
NetJ30_6: J30.6 R80.2 R89.2 | length 29.3
  Top w0.125: v2(17.5,32.359) 18.159,32.359 18.2,32.4 19.1,31.5 20.6,31.5 20.78,31.32 R89.2@20.78,30.436 R80.2@21.82,30.436
  Signal_7 w0.125: J30.6@2,33.5 3.5,33.5 4.3,34.3 4.3,36.2 5.471,37.371 6.693,37.371 8.068,35.996 8.068,32.532 8.9,31.7 12.363,31.7 13.693,33.03 13.944,33.03 14.158,33.244 16.615,33.244 v2(17.5,32.359)
NetJ30_9: J30.9 R118.2 R181.2 | length 32.7
  Top w0.125: J30.9@2,37.25 3.25,37.25 4.2,36.3 4.2,32.2 4.9,31.5 4.9,29.9 4.5,29.5 v2(3.8,29.5) ; v2(16.5,28.246) 17.146,27.6 R181.2@19.1,27.6 19.85,27.6 20.03,27.78 20.03,28.83 20.75,29.55 21.85,29.55 22.2,29.2 R118.2@22.2,28.78
  Signal_3 w0.125: v2(3.8,29.5) 4.7,29.5 5.803,30.603 6.878,30.603 6.975,30.7 7.325,30.7 8.2,30.7 8.9,30 13.2,30 13.6,29.6 15.146,29.6 v2(16.5,28.246)
NetJ30_13: J30.13 R253.1 R256.1 | length 8.4
  Top w0.125: J30.13@2,42 3.5,42 4.158,42.658 R256.1@4.158,44.32
  Bottom w0.125: J30.13@2,42.25 3.65,42.25 5,43.6 R253.1@5,44.385
NetJ31_2: J31.2 L5.2 | length 2.5
  Bottom w0.125: J31.2@12.601,65.2 12.601,63.899 12.975,63.525 L5.2@12.975,62.9
NetJ31_3: J31.3 L5.3 | length 2.4
  Bottom w0.125: L5.3@13.525,62.9 13.525,63.525 13.851,63.851 J31.3@13.851,65.2
NetJ31_5: J31.5 L30.2 | length 2.5
  Bottom w0.125: J31.5@16.351,65.2 16.351,63.899 16.725,63.525 L30.2@16.725,62.9
NetJ31_6: J31.6 L30.3 | length 2.4
  Bottom w0.125: L30.3@17.275,62.9 17.275,63.775 17.601,64.101 J31.6@17.601,65.2
NetJ31_8: J31.8 L31.2 | length 2.5
  Bottom w0.125: J31.8@20.101,65.2 20.101,64.149 20.475,63.775 L31.2@20.475,62.9
NetJ31_9: J31.9 L31.3 | length 2.4
  Bottom w0.125: L31.3@21.025,62.9 21.025,63.775 21.351,64.101 J31.9@21.351,65.2
NetJ31_11: J31.11 L32.2 | length 2.5
  Bottom w0.125: J31.11@23.851,65.2 23.851,64.149 24.225,63.775 L32.2@24.225,62.9
NetJ31_12: J31.12 L32.3 | length 2.4
  Bottom w0.125: L32.3@24.775,62.9 24.775,63.775 25.101,64.101 J31.12@25.101,65.2
NetJ31_14: J31.14 L33.2 | length 2.5
  Bottom w0.122: J31.14@27.601,65.2 27.601,64.149 27.975,63.775 L33.2@27.975,62.9
NetJ31_15: J31.15 L33.3 | length 2.4
  Bottom w0.122: L33.3@28.525,62.9 28.525,63.775 28.851,64.101 J31.15@28.851,65.2
NetJ31_16: J31.16 R258.2 R259.2 | length 4
  Top w0.125: R259.2@28.73,62.5 R258.2@28.73,63.75 v1(30,63.75)
  Bottom w0.125: v1(30,63.75) 30,65.099 J31.16@30.101,65.2
NetJ31_20: J31.20 L34.2 | length 2.4
  Bottom w0.5: L34.2@35,62.85 35.101,62.951 J31.20@35.101,65.2
NetJ33_1: J33.1 R255.2 | length 4.1
  Top w0.125: R255.2@60.5,18.48 60.5,19.104 61.146,19.75 J33.1@63.75,19.75
NetJ33_2: J33.2 R276.2 | length 3.2
  Top w0.125: R276.2@61.5,18.48 61.5,19 61.75,19.25 62.1,19.25 62.85,18.5 J33.2@63.75,18.5
NetJ33_3: J33.3 R277.2 | length 3.6
  Top w0.125: J33.3@63.75,17.25 65.8,17.25 66.05,17 R277.2@67.27,17
NetJ33_4: J33.4 R278.2 | length 3.5
  Top w0.125: J33.4@63.75,16 R278.2@67.27,16
NetL1_1: L1.1 R142.2 U23.2 U23.13 | length 13.2
  Signal_4 w0.25: v1(53.403,53.153) 53.447,53.153 53.482,53.118 53.482,51.7 53.682,51.5 53.682,50.718 54.6,49.8 56.88,49.8 58.68,51.6 v1(60.7,51.6)
  Bottom w0.125: R142.2@59.8,51.6 v1(60.7,51.6)
  Bottom w0.2: v1(53.375,53.75) U23.2@54.2,53.75 U23.13@55,53.75
  other v1: 51.25,56.75 51.25,57.5
NetL8_1: L8.1 U13.1 | length 3.3
  Bottom w0.125: U13.1@43.25,30.95 43.25,30.25 43.75,29.75 44.25,29.75 44.9,29.1 L8.1@44.9,28.6
NetL8_4: L8.4 U13.2 | length 3.1
  Bottom w0.125: U13.2@42.75,30.95 42.75,30.25 43.5,29.5 43.644,29.5 43.646,29.498 43.75,29.498 44.1,29.148 L8.4@44.1,28.6
NetL11_1: L11.1 U13.3 | length 2.7
  Bottom w0.125: U13.3@42.25,30.95 42.25,30.25 43.15,29.35 L11.1@43.15,28.6
NetL11_4: L11.4 U13.4 | length 2.6
  Bottom w0.125: U13.4@41.75,30.95 41.75,30 42.35,29.4 L11.4@42.35,28.6
NetL14_1: L14.1 U13.6 | length 2.6
  Bottom w0.125: L14.1@40.15,28.6 40.15,29.15 40.75,29.75 U13.6@40.75,30.95
NetL14_4: L14.4 U13.7 | length 2.7
  Bottom w0.125: L14.4@39.35,28.6 39.35,29.1 40.25,30 U13.7@40.25,30.95
NetL16_1: L16.1 U13.8 | length 3.1
  Bottom w0.125: L16.1@38.4,28.6 38.4,29.15 38.55,29.3 38.867,29.3 39.75,30.183 U13.8@39.75,30.95
NetL16_4: L16.4 U13.9 | length 3.5
  Bottom w0.125: L16.4@37.6,28.6 37.6,29.35 37.981,29.73 38.831,29.73 39.25,30.15 U13.9@39.25,30.95
NetNT1_1: NT1.1 U6.34 | length 27.1
  Top w0.125: NT1.1@69.027,3.3 69.375,3.3 69.5,3.425 v2(69.5,3.75)
  Signal_3 w0.125: v2(69.5,3.75) 65.7,7.55 65.7,19.85 67.07,21.22 68.024,21.22 68.219,21.025 71.275,21.025 71.95,21.7 v3(72.5,21.7)
  Bottom w0.125: v3(72.5,21.7) 72.51,21.71 U6.34@73.37,21.71
NetQ1_1: Q1.1 R13.2 | length 1.7
  Bottom w0.5: R13.2@89.38,22.2 89.85,22.67 Q1.1@89.85,23.7
NetQ2_D: Q2.D R72.2 U15.G | length 4.8
  Top w0.125: R72.2@37.305,30.625 37.775,30.155 U15.G@37.775,29.025 37.775,28.125 38.465,27.435 Q2.D@39.575,27.435
NetQ2_G: Q2.G R75.2 | length 1.5
  Top w0.125: Q2.G@40.075,28.815 40.08,28.82 R75.2@40.08,30.3
NetQ9_D: Q9.D R120.2 | length 2.5
  Top w0.125: Q9.D@92.4,51.69 92.4,51.9 v1(93.1,51.9)
  Bottom w0.125: R120.2@92.3,51.005 92.3,51.7 92.5,51.9 v1(93.1,51.9)
NetR1_2: R1.2 U11.C1 U11.C2 U11.F3 U11.G1 U11.G2 U11.G3 | length 5.1
  Top w0.125: U11.G3@80.83,51.6 v1(81.465,52.235) ; U11.G2@80.83,52.87 v1(81.465,53.505) ; U11.G1@80.83,54.14 v1(81.465,54.775) ; U11.F3@82.1,51.6 82.6,52.1 v1(82.6,52.2) ; U11.C2@85.91,52.87 86.44,53.4 v1(86.5,53.4) ; U11.C1@85.91,54.14 86.37,54.6 v1(86.5,54.6)
NetR2_2: R2.2 U11.H1 U11.H2 U11.H3 U11.J3 | length 3.6
  Top w0.125: U11.J3@78.29,51.6 v1(78.925,52.235) ; U11.H3@79.56,51.6 v1(80.195,52.235) ; U11.H2@79.56,52.87 v1(80.195,53.505) ; U11.H1@79.56,54.14 v1(80.195,54.775)
NetR9_2: R9.2 U24.7 | length 2.8
  Top w0.125: v2(22.5,49.5) 23,49.5 23.28,49.78 R9.2@23.28,50.4
  Bottom w0.125: v2(22.5,49.5) 22.9,49.5 23.389,49.011 U24.7@23.389,48.807
NetR10_2: R10.2 U24.8 | length 3.3
  Top w0.125: R10.2@23.28,51.6 23.746,51.6 23.9,51.446 v2(23.9,49.6)
  Bottom w0.125: U24.8@23.889,48.807 23.889,49.589 v2(23.9,49.6)
NetR15_2: R15.2 R18.2 U12.1 | length 4.8
  Top w0.125: R15.2@24.73,30.45 25.16,30.45 25.4,30.69 26.567,30.69 U12.1@26.605,30.729 26.605,31.295 25.646,32.254 R18.2@24.78,32.254
NetR16_1: R16.1 R19.1 R64.1 U12.2 | length 10.6
  Top w0.125: R16.1@24.1,28.78 25.28,28.78 25.959,29.459 U12.2@26.605,29.459 28.959,29.459 29.2,29.7 29.2,31.15 29.478,31.427 30.335,31.427 30.58,31.672 R64.1@30.58,32.2 32.016,32.2 R19.1@32.096,32.12
NetR39_2: R39.2 U11.K1 U11.K2 U11.K3 U11.P2 | length 5.1
  Top w0.125: U11.P2@71.94,52.87 71.94,53.14 v1(72.5,53.7) ; U11.K3@77.02,51.6 v1(77.655,52.235) ; U11.K2@77.02,52.87 v1(77.655,53.505) ; U11.K1@77.02,54.14 v1(77.655,54.775)
  Bottom w0.5: R39.2@76.4,54.9 76.4,54.775 v1(77.655,54.775)
NetR42_2: R42.2 U11.N1 | length 1.7
  Top w0.125: v1(72.6,54.9) 72.6,54.75 U11.N1@73.21,54.14
  Bottom w0.125: R42.2@72.58,55.6 72.575,55.595 72.6,55.57 v1(72.6,54.9)
NetR54_2: R54.2 U16.24 | length 3
  Bottom w0.125: R54.2@21.373,24.189 21.373,25.373 22.35,26.35 U16.24@22.75,26.35
NetR68_1: R68.1 U13.28 | length 3.9
  Bottom w0.125: U13.28@44.05,35.75 44.031,35.769 44.031,38.781 44.25,39 R68.1@44.25,39.52
NetR70_2: R70.2 U13.35 | length 2.7
  Bottom w0.125: U13.35@44.05,32.25 44.85,32.25 45.1,32 45.1,31.32 R70.2@45.72,30.7
NetR71_2: R71.2 U13.22 | length 5.5
  Bottom w0.125: R71.2@37.5,39.52 37.5,39 37.75,38.75 38.35,38.75 39.104,37.996 40.5,37.996 40.75,37.746 U13.22@40.75,36.55
NetR73_2: R73.2 U13.24 | length 4.1
  Bottom w0.125: R73.2@40,39.52 40,39 40.2,38.8 40.9,38.8 41.75,37.95 U13.24@41.75,36.55
NetR74_2: R74.2 U13.25 | length 3.4
  Bottom w0.125: R74.2@41.25,39.52 41.25,39 42.25,38 U13.25@42.25,36.55
NetR77_2: R77.2 U18.1 | length 2.2
  Top w0.127: v2(88,61.25) 88.03,61.22 R77.2@88.65,61.22
  Bottom w0.127: v2(88,61.25) 88.665,60.585 U18.1@88.665,60.03
NetR81_2: R81.2 R282.2 U27.24 | length 108.6
  Top w0.121: v1(46.25,22.5) 46.25,26.389 46.033,26.606 46.033,26.994 46.306,27.267 47.028,27.267 48.067,28.306 48.067,29.317 48.25,29.5 U27.24@48.55,29.5
  Signal_8 w0.125: v1(82.9,56.4) 89.3,56.4 90.2,55.5 90.2,55 92.2,53 92.2,52.993 92.219,52.974 92.219,49.019 91.801,48.601 91.801,47.09 92.066,46.825 92.066,42.643 92.778,41.932 92.778,40.174 92.873,40.079 92.873,38.73 92.25,38.107 92.25,36.64 91.478,35.868 91.478,35.178 89.555,33.255 89.555,32.991 89.279,32.715 87.815,32.715 87.328,32.228 87.328,29.07 87.2,28.942 87.2,27.6 87.7,27.1 87.7,26.056 86.899,25.255 86.655,25.255 v3(85.1,23.7)
  Signal_7 w0.125: v1(46.25,22.5) 46.836,22.5 47.306,22.97 47.694,22.97 48.164,22.5 55.464,22.5 56.32,23.356 56.395,23.431 60.273,23.431 61.742,24.9 65.931,24.9 65.985,24.847 70.204,24.847 71.873,26.516 71.873,29.473 72.171,29.771 73.45,29.771 73.598,29.92 75.92,29.92 78.455,29.919 78.706,30.17 79.356,30.17 79.795,29.73 81.594,29.73 81.764,29.9 82.564,29.9 83.076,29.388 83.076,29.2 83.5,28.777 83.5,23.1 84.173,22.427 84.9,22.427 85.218,22.745 85.218,23.582 v3(85.1,23.7)
  Bottom w0.121: R81.2@83.77,56.25 R282.2@83.77,57.4
  Bottom w0.125: v1(82.9,56.4) 83.62,56.4 R81.2@83.77,56.25
NetR91_1: R91.1 R92.2 U17.4 | length 3.7
  Top w0.25: R92.2@71.6,20.4 71.6,20.581 72.749,20.581 73.3,20.03 R91.1@73.4,20.03 73.77,20.4 U17.4@74.758,20.4
NetR94_2: R94.2 U6.5 | length 3.3
  Bottom w0.125: U6.5@80.23,23.31 81.51,23.31 82,23.8 82,24.4 82.1,24.5 R94.2@82.72,24.5
NetR123_2: R123.2 U18.4 | length 2.1
  Top w0.127: v2@84.85,61.305 v2(84.855,61.3) 85.68,61.3 R123.2@85.7,61.32
  Bottom w0.127: U18.4@84.855,60.03 v2(84.855,61.3)
NetR125_2: R125.2 U9.13 | length 2.4
  Top w0.127: U9.13@24.35,34.375 25.475,34.375 v2(25.65,34.55)
  Bottom w0.127: R125.2@24.78,34.2 25.3,34.2 v2(25.65,34.55)
NetR131_2: R131.2 U6.8 | length 1.9
  Bottom w0.125: U6.8@80.23,22.11 81.62,22.11 R131.2@82,21.73
NetR137_1: R137.1 R138.2 U23.4 | length 3.3
  Bottom w0.15: R138.2@52.5,56.67 52.5,56.1 52.73,55.87 R137.1@52.73,55.4 53.2,55.4 53.3,55.3 53.3,54.9 53.45,54.75 U23.4@54.2,54.75
NetR139_2: R139.2 U23.5 | length 1.7
  Bottom w0.25: R139.2@53.75,56.67 53.75,55.462 53.962,55.25 U23.5@54.2,55.25
NetR140_1: R140.1 R141.2 U23.9 | length 4.3
  Bottom w0.125: U23.9@55.8,54.25 56.55,54.25 56.9,54.6 57.6,54.6 58.1,54.1 R141.2@58.62,54.1 R140.1@58.62,53
NetR143_1: R143.1 R144.2 U23.7 | length 3.7
  Bottom w0.25: U23.7@55.8,55.25 56.3,55.25 56.5,55.45 R144.2@56.5,56.6 R143.1@58.25,56.6
NetR155_2: R155.2 U9.18 | length 2.4
  Top w0.127: U9.18@30.15,35.675 32.445,35.675 R155.2@32.5,35.73
NetR157_2: R157.2 U24.24 | length 3.1
  Bottom w0.125: R157.2@22.38,42.3 22.38,43.38 23.389,44.389 U24.24@23.389,45.007
NetR179_1: R179.1 R180.2 R183.1 U26.4 | length 5
  Top w0.125: R180.2@86.18,59.837 87.83,59.837 R179.1@87.88,59.887 87.98,59.787 U26.4@89.58,59.787 89.77,59.977 R183.1@89.77,61.207
NetR189_2: R189.2 U6.10 | length 3.6
  Bottom w0.125: U6.10@80.23,21.31 80.88,21.31 81.1,21.09 81.1,19.744 81.66,19.184 R189.2@81.66,18.73
NetR190_2: R190.2 U6.9 | length 4.7
  Bottom w0.125: U6.9@80.23,21.71 80.89,21.71 81.4,21.2 81.4,19.8 81.897,19.303 82.297,19.303 82.87,18.73 R190.2@82.91,18.73
NetR191_2: R191.2 U6.7 | length 3.7
  Bottom w0.125: U6.7@80.23,22.51 82.99,22.51 83.2,22.3 R191.2@83.2,21.68
NetR192_2: R192.2 U6.2 | length 3.9
  Bottom w0.125: U6.2@80.23,24.51 80.76,24.51 81.348,25.098 81.348,25.104 81.372,25.128 81.378,25.128 81.772,25.522 81.772,25.528 82.052,25.808 82.052,26.252 82.4,26.6 R192.2@83.02,26.6
NetR193_2: R193.2 U6.4 | length 3.9
  Bottom w0.125: U6.4@80.23,23.71 80.23,23.682 81.282,23.682 81.6,24 81.6,24.994 82.024,25.417 82.024,25.424 82.2,25.6 R193.2@82.72,25.6
NetR194_2: R194.2 U6.54 | length 9.8
  Signal_3 w0.125: v2(79.5,26.8) 83.1,26.8 83.422,27.122 84.865,27.122 85.118,26.869 85.118,26.018 v1(85.1,26)
  Bottom w0.125: U6.54@78.6,25.74 78.6,26.2 79.1,26.7 79.46,26.7 79.5,26.74 v2(79.5,26.8) ; v1(85.1,26) 85.4,26 85.62,25.78 R194.2@85.62,25
NetR195_2: R195.2 U6.1 | length 4.6
  Bottom w0.125: U6.1@80.23,24.91 80.803,24.91 81.096,25.203 81.096,25.209 81.268,25.38 81.274,25.38 81.52,25.626 81.52,25.632 81.8,25.913 81.8,27 82.5,27.7 R195.2@83.02,27.7
NetR227_2: R227.2 R229.2 U28.3 | length 56.4
  Top w0.125: R229.2@56.48,25.8 R227.2@57.62,25.8 57.466,25.646 57.466,25.315 57.3,25.149 v2(56.599,25.149)
  Signal_8 w0.125: v2(44.7,67.6) 44.7,65.307 45.326,64.68 47.84,64.68 48.748,63.772 48.748,61.748 47.808,60.808 47.808,48.708 46.37,47.27 46.37,45.837 45.741,45.209 45.741,42.405 45.665,42.329 45.665,41.921 47.1,40.486 47.578,40.486 48.78,39.284 48.78,38.806 49.056,38.53 49.058,38.53 49.476,38.113 49.476,34.703 50.33,33.848 50.33,29.47 53.4,26.4 54.9,26.4 56.151,25.149 v2(56.599,25.149)
  Bottom w0.125: U28.3@44.3,66.8 44.3,67.2 v2(44.7,67.6)
NetR228_2: R228.2 R230.2 U28.5 | length 51.3
  Top w0.125: R230.2@56.48,27 56.58,27.1 v2(57,27.1) 57.52,27.1 R228.2@57.62,27
  Signal_8 w0.125: v2(45.5,65.1) 48.1,65.1 49.1,64.1 49.1,61.4 48.06,60.36 48.06,47.11 46.43,45.48 46.43,42.505 46.72,42.216 46.72,41.955 49.107,39.568 49.346,39.568 50.03,38.884 50.03,38.045 50.65,37.425 50.65,34.652 51,34.302 51,29.982 54.251,26.73 55.83,26.73 56.2,27.1 v2(57,27.1)
  Bottom w0.125: U28.5@44.3,65.3 45.025,65.3 45.225,65.1 v2(45.5,65.1)
NetR263_1: R263.1 U18.5 | length 2.1
  Bottom w0.125: R263.1@84.73,67 84.73,65.095 U18.5@84.855,64.97
NetR264_1: R264.1 U19.5 | length 2.1
  Bottom w0.125: R264.1@90.23,67 90.23,65.095 U19.5@90.355,64.97
NetR270_1: R270.1 U11.V5 | length 5.4
  Top w0.125: v1(66.2,49.5) 66.42,49.5 U11.V5@66.86,49.06
  Bottom w0.125: v1(66.2,49.5) 66.2,49.67 66.75,50.22 66.75,52 67.52,52.77 R270.1@67.52,53.5
NetR271_1: R271.1 U11.Y4 | length 32.2
  Top w0.125: v1(63.685,50.965) U11.Y4@64.32,50.33 ; v1(78,67.75) R271.1@78.72,67.75
  Signal_8 w0.125: v1(63.685,50.965) 63.685,50.015 64.475,49.225 65.149,49.225 65.425,49.501 65.425,50.989 65.936,51.5 66.649,51.5 67.369,52.22 68.372,52.22 70.5,54.348 70.5,54.576 70.505,54.581 70.505,54.619 70.504,54.905 70.272,55.137 70.272,55.737 70.276,55.741 70.276,55.9 70.504,56.128 70.504,56.462 70.505,57.432 70.23,57.706 70.23,64.33 73.65,67.75 v1(78,67.75)
NetR272_1: R272.1 U11.W13 | length 3.3
  Top w0.125: v1(64.955,38.265) U11.W13@65.59,38.9
  Bottom w0.125: v1(64.955,38.265) 65.6,38.91 65.6,39.57 65.73,39.7 R272.1@65.73,40.32
NetR273_1: R273.1 U11.T19 | length 46.3
  Top w0.125: v1(68.8,31.3) 68.82,31.28 U11.T19@69.4,31.28 ; R273.1@77.23,65.5 v1(78,65.5)
  Signal_8 w0.125: v1(68.8,31.3) 68.064,31.3 67.694,31.669 67.031,31.669 66.695,32.005 66.695,35.869 66.394,36.17 66.387,36.17 65.755,36.801 65.755,38.706 65.975,38.925 66.279,38.925 66.695,39.341 66.695,40.305 65.755,41.245 65.755,44.062 65.501,44.315 65.501,44.915 65.677,45.09 65.677,50.171 66.001,50.495 66.419,50.495 66.695,50.771 66.695,51.189 67.473,51.968 68.668,51.968 70.835,54.136 70.835,54.969 71.269,55.403 71.269,58.093 73.6,60.423 73.6,63.6 75.5,65.5 v1(78,65.5)
NetR283_1: R283.1 U11.V15 | length 17
  Top w0.127: R283.1@58.8,33.12 58.93,33.25 v2(59.35,33.25) ; v1(66.2,35.7) U11.V15@66.86,36.36
  Bottom w0.127: v2(59.35,33.25) 58.585,34.015 58.585,36.8 59.505,37.72 62.711,37.72 62.886,37.546 62.886,36.686 62.15,35.95 62.15,35.487 62.537,35.1 65.6,35.1 v1(66.2,35.7)
NetTP1_1: TP1.1 U11.D3 | length 7.7
  Top w0.125: U11.D3@84.64,51.6 v1(85.275,52.235)
  Bottom w0.125: v1(85.275,52.235) 85.745,52.705 88.63,52.705 89.014,52.321 90.929,52.321 TP1.1@91.5,51.75
NetTP2_1: TP2.1 U11.D9 | length 9
  Top w0.1: U11.D9@84.64,43.98 85.275,44.615 85.3,44.59 v1(85.3,44.54)
  Bottom w0.125: v1(85.3,44.54) 87.36,44.54 88.552,45.732 88.552,47.286 89.016,47.75 89.25,47.75 89.6,48.1 89.6,48.896 89.246,49.25 TP2.1@89.25,49.25
NetTP3_1: TP3.1 U11.D8 | length 10.9
  Top w0.125: U11.D8@84.64,45.25 v1(85.275,45.885)
  Bottom w0.125: v1(85.275,45.885) 87.021,45.885 87.376,45.53 87.994,45.53 88.3,45.836 88.3,51.5 88.55,51.75 TP3.1@89.25,51.75
NetTP4_1: TP4.1 U11.C12 | length 13.6
  Top w0.1: U11.C12@85.91,40.17 v1(86.545,40.805)
  Bottom w0.125: v1(86.545,40.805) 88.2,42.46 88.2,44.444 90.956,47.2 93.124,47.2 93.75,47.826 TP4.1@93.75,49.25
NetTP5_1: TP5.1 U11.L3 | length 2.1
  Top w0.1: v1(75.115,52.235) U11.L3@75.75,51.6
  Bottom w0.125: TP5.1@73.9,52.2 75.08,52.2 v1(75.115,52.235)
NetTP8_1: TP8.1 U11.D12 | length 13.3
  Top w0.125: U11.D12@84.64,40.17 v1(85.275,39.535)
  Bottom w0.125: v1(85.275,39.535) 85.275,40.199 86.351,41.275 86.475,41.275 87.8,42.6 87.8,44.4 91.5,48.1 TP8.1@91.5,49.245
NetTP16_1: TP16.1 U11.E2 | length 1.8
  Top w0.125: U11.E2@83.37,52.87 83.67,52.87 v1(84.1,53.3)
  Bottom w0.125: TP16.1@83.4,52.8 83.9,53.3 v1(84.1,53.3)
NetU30_4: U30.4 U31.19 | length 37.6
  Top w0.125: U30.4@11.3,36.85 11.9,36.85 12.5,36.25 13,36.25 14.2,37.45 14.2,38.257 13.851,38.605 13.851,42.376 14.275,42.8 14.8,42.8 15.418,43.418 15.418,48.582 v3(14.75,49.25) ; U31.19@32.775,51.85 v1(32.775,53.007)
  Signal_3 w0.125: v3(14.75,49.25) 17.38,51.88 25.874,51.88 26.177,52.183 31.951,52.183 v1(32.775,53.007)
NTAG/IOEXP_I2C1_SCL: R229.1 R265.1 U27.34 | length 5.7
  Top w0.119: U27.34@53.75,28.8 53.75,27.151 55.101,25.8 R229.1@55.52,25.8 56,25.32 56,25.093 ; 56,25.08 R265.1@56.6,24.48
NTAG/IOEXP_I2C1_SDA: R230.1 R247.1 U27.35 | length 5
  Top w0.119: U27.35@54.25,28.8 54.25,27.09 54.607,26.733 54.993,26.733 55.26,27 R230.1@55.52,27 55.9,27.38 55.9,27.8 56.2,28.1 R247.1@56.62,28.1
NTAG_FD: R201.2 R202.2 R205.2 U28.4 | length 4.3
  Bottom w0.119: U28.4@44.55,66.05 45.35,66.05 45.7,65.7 R201.2@46.22,65.7 R205.2@46.22,68.2
NTAG_FD/IO35: R205.1 U27.45 | length 49.9
  Top w0.119: U27.45@55.45,33.5 55.88,33.5 56.202,33.822 56.526,33.822 56.899,33.45 v3(56.9,33.45)
  Signal_8 w0.127: v2(48,68.2) 49.97,66.23 49.97,61.78 51.72,60.03 51.72,54.614 51.2,54.093 51.2,51.865 51.47,51.595 51.47,48.874 51.921,48.424 51.921,48.076 51.638,47.793 51.638,46.432 50.729,45.523 50.729,44.473 v1(50.461,44.205) ; v3(56.9,33.45) 57.321,33.87 57.321,34.845 57.25,34.915 57.25,36.15 58.046,36.946 58.046,40.696 58.95,41.6 58.95,42.685 58.8,42.835 58.8,43.315 v1(59.3,43.816)
  Signal_7 w0.127: v1(50.461,44.205) 50.884,44.205 50.976,44.297 52.403,44.297 53,43.7 55.3,43.7 55.359,43.759 59.244,43.759 v1(59.3,43.816)
  Bottom w0.119: R205.1@47.18,68.2 v2(48,68.2)
NTAG_I2C_SCL: R199.2 R227.1 | length 7.9
  Top w0.119: R227.1@58.58,25.8 58.58,25.12 58.6,25.1 v2(58.7,25.1) ; v2(60.1,21.9) 60.1,22.37 R199.2@60.25,22.52
  Signal_3 w0.127: v2(58.7,25.1) 58.7,24.7 57.62,23.62 57.62,22.23 58,21.85 58.625,21.85 59.05,22.275 59.875,22.275 60.1,22.05 v2(60.1,21.9)
NTAG_I2C_SDA: R200.2 R228.1 | length 2.4
  Top w0.119: R228.1@58.58,27 59,27 59.5,26.5 59.9,26.5 60.25,26.15 R200.2@60.25,25.73
NTAG_VCC: C146.2 D14.3 R202.1 U28.6 | length 10.1
  Top w0.2: v1(44.5,63.25) D14.3@44.5,64.4
  Signal_4 w0.25: v1(44.5,63.25) 45.732,63.25 46.318,63.836 46.318,64 46.6,64.282 46.7,64.282 46.7,65.7 v2(47.9,66.9)
  Bottom w0.125: R202.1@47.18,66.95 47.85,66.95 v2(47.9,66.9)
  Bottom w0.2: U28.6@43.8,65.3 43.8,64.24 C146.2@44.04,64
  Bottom w0.25: C146.2@44.04,64 44.408,63.632 44.408,63.342 v1(44.5,63.25)
NTAG_VOUT: C144.2 C145.2 R204.2 U28.7 | length 5
  Top w0.2: R204.2@42.5,65.52 42.5,65 43.1,64.4 v1(43.1,63.9)
  Bottom w0.127: C144.2@42.46,63.25 42.46,63.26 v1(43.1,63.9) 43.06,63.9 C145.2@42.46,64.5 42.86,64.9 43.15,64.9 43.3,65.05 U28.7@43.3,65.3
ON/OFF: R167.2 U11.W14 | length 84.8
  Top w0.119: v1(64.955,36.995) U11.W14@65.59,37.63
  Signal_3 w0.127: v1(16.5,44.1) 16.5,44 17.793,42.707 20.668,42.707 21.1,42.276 21.7,42.276 22.546,43.121 22.546,44.871 23.205,45.529 23.895,45.529 24.936,46.57 25.695,46.57 26.22,46.045 29.172,46.045 31.391,43.826 37.48,43.826 37.699,44.045 46.289,44.045 46.518,44.274 47.679,44.274 48.027,43.926 48.991,43.926 50.577,42.34 50.821,42.34 50.823,42.338 51.649,42.338 53.743,40.245 58.18,40.245 59.184,39.241 60.969,39.241 61.474,38.736 62.61,38.736 62.886,38.46 62.886,38.399 63.565,37.72 63.79,37.72 64.515,36.995 v1(64.955,36.995)
  Signal_8 w0.127: v3(13.8,32.5) 14.3,32.5 14.946,33.146 14.946,34.096 17.474,36.625 17.474,41.226 16.8,41.9 16.8,43.7 16.5,44 v1(16.5,44.1)
  Signal_7 w0.127: v3(13.8,32.5) 13.8,32.45 14.293,31.957 14.293,31.007 16,29.3 16,28.7 15.826,28.525 15.826,27.967 16,27.792 16,27.554 15.967,27.52 15.926,27.52 15.68,27.274 15.68,26.926 15.826,26.78 15.826,24.774 18.5,22.1 v1(18.5,22)
  Bottom w0.119: R167.2@18.5,21.23 v1(18.5,22)
OTGD_N: J16.2 L10.2 U20.4 | length 21.5
  Top w0.127: v1(52.65,15.7) 52.8,15.85 U20.4@52.8,17.35
  Signal_8 w0.165: v1(52.65,15.7) 52.2,16.15 52.2,16.3 52.325,16.425 52.775,16.425 52.9,16.55 52.9,16.7 52.5,17.1 50.7,17.1 50,16.4 50,9 51.032,7.968 51.852,7.968 52.384,7.436 52.384,6.915 v1(53.3,6)
  Bottom w0.127: J16.2@52.65,4.15 52.65,4.913 L10.2@52.65,5.9 52.75,6 v1(53.3,6)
